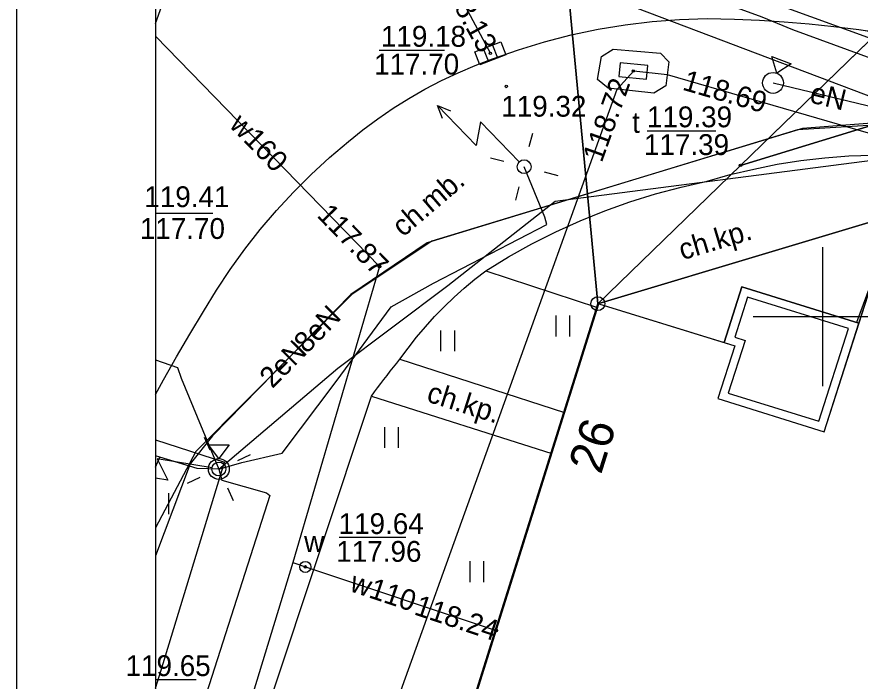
# Model space of a CAD drawing. Extents: x 6432121 to 6432331, y 5662538 to 5662686.
# Drawn here: x 6432120.98 to 6432151.36, y 5662586.88 to 5662610.8 of the extents above; entities that cross this region are included whole.
import ezdxf

# ---------------------------------------------------------------- set-up
doc = ezdxf.new("R2010")
doc.units = 0
for name, color, linetype in [('Warstwa 1', 7, 'Continuous'), ('Warstwa 10', 7, 'Continuous'), ('Warstwa 12', 7, 'Continuous'), ('Warstwa 13', 7, 'Continuous'), ('Warstwa 14', 7, 'Continuous'), ('Warstwa 15', 7, 'Continuous'), ('Warstwa 16', 7, 'Continuous'), ('Warstwa 2', 7, 'Continuous'), ('Warstwa 20', 7, 'Continuous'), ('Warstwa 25', 7, 'Continuous'), ('Warstwa 35', 7, 'Continuous'), ('Warstwa 4', 7, 'Continuous'), ('Warstwa 40', 7, 'Continuous'), ('Warstwa 5', 7, 'Continuous'), ('Warstwa 6', 7, 'Continuous'), ('Warstwa 63', 7, 'Continuous'), ('Warstwa 8', 7, 'Continuous'), ('Warstwa 9', 7, 'Continuous')]:
    doc.layers.add(name, color=color, linetype=linetype)

msp = doc.modelspace()

# ---------------------------------------------------------------- linework, layer by layer
at = {"layer": 'Warstwa 1'}
for p, q in [((6432136.954, 5662653.004), (6432141.907, 5662600.47)), ((6432136.954, 5662653.004), (6432141.907, 5662600.47)), ((6432147.05, 5662605.45), (6432164.332, 5662622.19)), ((6432147.05, 5662605.45), (6432164.332, 5662622.19)), ((6432147.05, 5662605.45), (6432180.9, 5662615.82)), ((6432147.05, 5662605.45), (6432180.9, 5662615.82)), ((6432141.907, 5662600.47), (6432147.05, 5662605.45)), ((6432141.907, 5662600.47), (6432147.05, 5662605.45)), ((6432141.907, 5662600.47), (6432155.186, 5662604.45)), ((6432141.907, 5662600.47), (6432155.186, 5662604.45)), ((6432128.788, 5662558.646), (6432141.907, 5662600.47)), ((6432128.788, 5662558.646), (6432141.907, 5662600.47))]:
    msp.add_line(p, q, dxfattribs=at)
msp.add_lwpolyline([(6432127.995, 5662556.053), (6432141.94, 5662600.47), (6432146.84, 5662598.95), (6432146.23, 5662597.05), (6432150.06, 5662595.86), (6432151.74, 5662601.09), (6432197.45, 5662586.76), (6432193.11, 5662572.86), (6432152.51, 5662585.63), (6432148.5, 5662572.83), (6432147.6, 5662573.08), (6432145.6, 5662566.71), (6432142.254, 5662556.053)], dxfattribs=at)
at = {"layer": 'Warstwa 10'}
msp.add_circle((6432141.907, 5662600.47), 0.25, dxfattribs=at)
at = {"layer": 'Warstwa 12'}
for points in [[(6432138.036, 5662609.488), (6432134.626, 5662615.865), (6432132.697, 5662619.588), (6432131.739, 5662621.489)], [(6432127.185, 5662618.897), (6432135.629, 5662615.848), (6432142.79, 5662613.281), (6432154.997, 5662608.849), (6432160.46, 5662606.879), (6432165.736, 5662604.745), (6432167.852, 5662603.89), (6432175.869, 5662600.716), (6432188.607, 5662595.673), (6432197.141, 5662592.258), (6432208.285, 5662587.853), (6432217.328, 5662584.25), (6432226.269, 5662580.703), (6432229.116, 5662579.575), (6432234.631, 5662577.404), (6432234.076, 5662575.247), (6432232.817, 5662570.334), (6432230.472, 5662561.671), (6432228.926, 5662556.053)], [(6432228.367, 5662556.053), (6432231.658, 5662568.249), (6432233.96, 5662576.659), (6432221.597, 5662581.652), (6432210.31, 5662586.256), (6432196.752, 5662591.605), (6432184.96, 5662596.314), (6432169.081, 5662602.651), (6432160.264, 5662606.196), (6432148.936, 5662610.33), (6432147.827, 5662610.792), (6432135.842, 5662615.166), (6432127.959, 5662618.065)], [(6432127.946, 5662615.962), (6432128.842, 5662616.521), (6432129.879, 5662616.161), (6432135.004, 5662614.244), (6432137.96, 5662613.1), (6432142.879, 5662611.278), (6432154.141, 5662607.021), (6432159.281, 5662605.095), (6432161.845, 5662604.079), (6432162.876, 5662603.668), (6432169.279, 5662601.311), (6432171.448, 5662600.465), (6432177.657, 5662598.132), (6432182.74, 5662596.197), (6432190.963, 5662593.097), (6432191.954, 5662592.706)], [(6432125.976, 5662610.557), (6432127.485, 5662614.793), (6432127.946, 5662615.962)], [(6432125.976, 5662610.102), (6432134.04, 5662601.81), (6432130.92, 5662591.15), (6432126.07, 5662575.26), (6432125.976, 5662574.953)], [(6432125.976, 5662559.881), (6432127.22, 5662563.81), (6432133.93, 5662584.09), (6432142.61, 5662608.19), (6432143.204, 5662608.85), (6432144.41, 5662608.72), (6432156.66, 5662605.17), (6432161.55, 5662603.82), (6432185, 5662594.71), (6432189.43, 5662592.42), (6432210.16, 5662585.32), (6432215.53, 5662583.54), (6432216.154, 5662583.288)], [(6432155.597, 5662608.32), (6432155.5, 5662607.86), (6432154.42, 5662607.05), (6432149.1, 5662606.73), (6432135.76, 5662602.66), (6432133.01, 5662600.8), (6432128.02, 5662595.71), (6432127.22, 5662594.7), (6432125.976, 5662591.383)], [(6432155.587, 5662608.308), (6432155.49, 5662607.98), (6432153.65, 5662607.11), (6432149.28, 5662606.78), (6432135.93, 5662602.72), (6432133.04, 5662600.8), (6432127.42, 5662595.15), (6432125.976, 5662592.393)], [(6432128.254, 5662594.515), (6432132.54, 5662598.15), (6432136.498, 5662601.127), (6432140.369, 5662604.156), (6432151.789, 5662605.642), (6432152.962, 5662605.787), (6432154.261, 5662607.985), (6432155.266, 5662607.612), (6432155.378, 5662607.878), (6432155.597, 5662608.32)], [(6432148.22, 5662608.42), (6432153.65, 5662607.11), (6432155.49, 5662607.98), (6432155.587, 5662608.308)], [(6432128.254, 5662594.515), (6432129.083, 5662594.753), (6432130.54, 5662595.089), (6432132.478, 5662597.669), (6432134.467, 5662600.362), (6432135.993, 5662601.204), (6432140.071, 5662603.327), (6432139.999, 5662603.585), (6432139.251, 5662605.402)], [(6432152.099, 5662602.16), (6432151.23, 5662599.79)], [(6432125.976, 5662598.445), (6432126.766, 5662598.169), (6432126.89, 5662597.793), (6432128.254, 5662594.515)], [(6432126.133, 5662594.937), (6432125.976, 5662594.984)], [(6432125.976, 5662594.576), (6432126.133, 5662594.937)], [(6432128.254, 5662594.515), (6432127.475, 5662594.536), (6432126.133, 5662594.937)], [(6432128.254, 5662594.515), (6432128.361, 5662594.113), (6432129.97, 5662593.659), (6432130.096, 5662593.561), (6432127.399, 5662585.174), (6432125.976, 5662580.765)], [(6432130.92, 5662591.15), (6432131.37, 5662590.99), (6432138.244, 5662588.699)]]:
    msp.add_lwpolyline(points, dxfattribs=at)
msp.add_circle((6432147.05, 5662605.45), 0.045, dxfattribs=at)
at = {"layer": 'Warstwa 14'}
for p, q in [((6432134.032, 5662609.598), (6432136.387, 5662609.598)), ((6432143.682, 5662606.698), (6432146.155, 5662606.698)), ((6432125.976, 5662603.734), (6432128.034, 5662603.734)), ((6432134.995, 5662592.05), (6432132.594, 5662592.05)), ((6432125.976, 5662586.933), (6432127.442, 5662586.933))]:
    msp.add_line(p, q, dxfattribs=at)
for centre in [(6432138.036, 5662609.488), (6432138.036, 5662609.488), (6432138.036, 5662609.488), (6432143.185, 5662608.847), (6432143.185, 5662608.847), (6432143.185, 5662608.847), (6432143.185, 5662608.847), (6432134.04, 5662601.81), (6432131.37, 5662590.99), (6432131.37, 5662590.99), (6432138.244, 5662588.699)]:
    msp.add_circle(centre, 0.045, dxfattribs=at)
at = {"layer": 'Warstwa 16'}
msp.add_lwpolyline([(6432142.46, 5662609.63), (6432144.17, 5662609.49), (6432144.47, 5662609.18), (6432144.36, 5662608.31), (6432143.93, 5662608.05), (6432142.28, 5662608.23), (6432141.9, 5662608.54), (6432142.04, 5662609.37)], close=True, dxfattribs=at)
at = {"layer": 'Warstwa 2'}
for centre in [(6432139.251, 5662605.402), (6432128.254, 5662594.515)]:
    msp.add_circle(centre, 0.25, dxfattribs=at)
at = {"layer": 'Warstwa 20'}
msp.add_line((6432138.323, 5662588.936), (6432138.165, 5662588.462), dxfattribs=at)
at = {"layer": 'Warstwa 25'}
msp.add_circle((6432138.611, 5662608.293), 0.045, dxfattribs=at)
at = {"layer": 'Warstwa 35'}
for points in [[(6432151.315, 5662599.768), (6432147.1, 5662601.08), (6432146.462, 5662599.067), (6432146.84, 5662598.95), (6432146.23, 5662597.05), (6432150.06, 5662595.86)], [(6432150.937, 5662599.571), (6432147.296, 5662600.705), (6432146.839, 5662599.264), (6432147.218, 5662599.147), (6432146.608, 5662597.247), (6432149.865, 5662596.235)]]:
    msp.add_lwpolyline(points, close=True, dxfattribs=at)
at = {"layer": 'Warstwa 4'}
for p, q in [((6432137.782, 5662609.657), (6432137.964, 5662609.191)), ((6432138.108, 5662609.785), (6432138.29, 5662609.319))]:
    msp.add_line(p, q, dxfattribs=at)
for points in [[(6432137.479, 5662609.539), (6432138.411, 5662609.903), (6432138.593, 5662609.437), (6432137.661, 5662609.073)], [(6432143.707, 5662609.047), (6432142.712, 5662609.144), (6432142.663, 5662608.647), (6432143.658, 5662608.55)]]:
    msp.add_lwpolyline(points, close=True, dxfattribs=at)
for points in [[(6432139.439, 5662606.128), (6432139.564, 5662606.612)], [(6432138.525, 5662605.59), (6432138.041, 5662605.715)], [(6432139.977, 5662605.214), (6432140.461, 5662605.089)], [(6432139.063, 5662604.676), (6432138.938, 5662604.192)], [(6432127.995, 5662556.053), (6432141.94, 5662600.47), (6432146.84, 5662598.95), (6432146.23, 5662597.05), (6432150.06, 5662595.86), (6432151.74, 5662601.09), (6432197.45, 5662586.76), (6432193.11, 5662572.86), (6432152.51, 5662585.63), (6432148.5, 5662572.83), (6432147.6, 5662573.08), (6432142.254, 5662556.053)], [(6432127.943, 5662595.197), (6432127.735, 5662595.652)], [(6432128.936, 5662594.826), (6432129.391, 5662595.034)], [(6432127.572, 5662594.204), (6432127.117, 5662593.996)], [(6432128.565, 5662593.833), (6432128.773, 5662593.378)]]:
    msp.add_lwpolyline(points, dxfattribs=at)
msp.add_circle((6432131.37, 5662590.99), 0.2, dxfattribs=at)
at = {"layer": 'Warstwa 40'}
for points in [[(6432148.352, 5662608.771), (6432148.176, 5662609.371), (6432148.878, 5662609.108)], [(6432128.254, 5662594.89), (6432127.879, 5662595.39), (6432128.629, 5662595.39)]]:
    msp.add_lwpolyline(points, close=True, dxfattribs=at)
for points in [[(6432139.077, 5662605.581), (6432137.683, 5662607.016), (6432137.529, 5662606.169), (6432136.136, 5662607.604)], [(6432136.316, 5662607.137), (6432136.136, 5662607.604), (6432136.597, 5662607.41)], [(6432128.007, 5662594.556), (6432126.034, 5662594.884), (6432126.413, 5662594.111), (6432125.976, 5662594.184)]]:
    msp.add_lwpolyline(points, dxfattribs=at)
for centre, radius in [((6432148.22, 5662608.42), 0.375), ((6432139.251, 5662605.402), 0.25), ((6432128.254, 5662594.515), 0.375), ((6432128.254, 5662594.515), 0.25)]:
    msp.add_circle(centre, radius, dxfattribs=at)
at = {"layer": 'Warstwa 5'}
for p, q in [((6432137.478, 5662601.348), (6432137.87, 5662601.65)), ((6432137.87, 5662601.65), (6432141.897, 5662600.334)), ((6432137.097, 5662601.032), (6432137.478, 5662601.348)), ((6432136.728, 5662600.703), (6432137.097, 5662601.032)), ((6432136.371, 5662600.361), (6432136.728, 5662600.703)), ((6432136.026, 5662600.006), (6432136.371, 5662600.361)), ((6432140.71, 5662596.553), (6432141.897, 5662600.334)), ((6432135.694, 5662599.639), (6432136.026, 5662600.006)), ((6432140.402, 5662599.292), (6432140.402, 5662600.042)), ((6432140.902, 5662599.292), (6432140.902, 5662600.042)), ((6432135.375, 5662599.26), (6432135.694, 5662599.639)), ((6432136.254, 5662598.755), (6432136.254, 5662599.505)), ((6432136.754, 5662598.755), (6432136.754, 5662599.505)), ((6432135.071, 5662598.871), (6432135.375, 5662599.26)), ((6432134.78, 5662598.47), (6432135.071, 5662598.871)), ((6432134.78, 5662598.47), (6432140.71, 5662596.553)), ((6432125.976, 5662573.776), (6432133.75, 5662597.14)), ((6432133.75, 5662597.14), (6432140.245, 5662595.072)), ((6432134.232, 5662595.277), (6432134.232, 5662596.027)), ((6432134.732, 5662595.277), (6432134.732, 5662596.027)), ((6432125.976, 5662595.561), (6432128.463, 5662594.756)), ((6432127.995, 5662556.053), (6432140.245, 5662595.072)), ((6432126.164, 5662587.231), (6432128.463, 5662594.756)), ((6432126.449, 5662592.89), (6432126.449, 5662593.64)), ((6432137.304, 5662590.444), (6432137.304, 5662591.194)), ((6432137.804, 5662590.444), (6432137.804, 5662591.194)), ((6432125.976, 5662586.625), (6432126.164, 5662587.231))]:
    msp.add_line(p, q, dxfattribs=at)
at = {"layer": 'Warstwa 6'}
for points in [[(6432234.842, 5662644.244), (6432245.39, 5662639.916), (6432244.087, 5662648.722), (6432241.262, 5662679.658), (6432232.544, 5662677.413), (6432183.398, 5662664.76), (6432164.325, 5662660.371), (6432136.954, 5662653.004), (6432141.907, 5662600.47), (6432147.05, 5662605.45), (6432164.332, 5662622.19), (6432166.394, 5662623.975)], [(6432164.332, 5662622.19), (6432147.05, 5662605.45), (6432180.9, 5662615.82)], [(6432180.9, 5662615.82), (6432147.05, 5662605.45), (6432141.907, 5662600.47), (6432155.186, 5662604.45), (6432246.621, 5662569.177), (6432269.007, 5662560.534), (6432263.163, 5662588.197), (6432259.074, 5662585.787)]]:
    msp.add_lwpolyline(points, close=True, dxfattribs=at)
for points in [[(6432127.651, 5662556.053), (6432128.788, 5662558.646), (6432141.907, 5662600.47), (6432136.954, 5662653.004), (6432125.976, 5662650.322)], [(6432138.114, 5662609.287), (6432139.045, 5662609.616), (6432139.991, 5662609.903), (6432140.948, 5662610.148), (6432141.915, 5662610.352), (6432142.89, 5662610.512), (6432143.871, 5662610.629), (6432144.856, 5662610.704), (6432145.844, 5662610.735), (6432146.832, 5662610.722)], [(6432146.832, 5662610.722), (6432147.73, 5662610.683), (6432148.626, 5662610.625), (6432149.521, 5662610.549), (6432150.415, 5662610.453), (6432151.306, 5662610.339), (6432152.194, 5662610.206), (6432153.08, 5662610.054), (6432153.962, 5662609.883), (6432154.84, 5662609.694)], [(6432132.928, 5662606.31), (6432133.447, 5662606.729), (6432133.983, 5662607.128), (6432134.534, 5662607.505), (6432135.1, 5662607.861), (6432135.679, 5662608.193), (6432136.271, 5662608.502), (6432136.875, 5662608.788), (6432137.489, 5662609.05), (6432138.114, 5662609.287)], [(6432127.703, 5662600.183), (6432128.169, 5662600.953), (6432128.666, 5662601.703), (6432129.192, 5662602.432), (6432129.748, 5662603.14), (6432130.331, 5662603.824), (6432130.942, 5662604.485), (6432131.579, 5662605.12), (6432132.242, 5662605.729), (6432132.928, 5662606.31)], [(6432249.006, 5662556.053), (6432246.621, 5662569.177), (6432155.186, 5662604.45), (6432141.907, 5662600.47), (6432128.788, 5662558.646), (6432132.46, 5662567.032), (6432163.983, 5662578.631), (6432172.647, 5662574.865), (6432180.454, 5662556.053)], [(6432125.976, 5662597.203), (6432126.258, 5662597.729), (6432126.723, 5662598.557), (6432127.205, 5662599.375), (6432127.703, 5662600.183)]]:
    msp.add_lwpolyline(points, dxfattribs=at)
at = {"layer": 'Warstwa 63'}
for p, q in [((6432150, 5662602.5), (6432150, 5662597.5)), ((6432152.5, 5662600), (6432147.5, 5662600))]:
    msp.add_line(p, q, dxfattribs=at)
for points in [[(6432120.976, 5662686.053), (6432330.976, 5662686.053), (6432330.976, 5662537.553), (6432120.976, 5662537.553)], [(6432125.976, 5662556.053), (6432325.976, 5662556.053), (6432325.976, 5662681.053), (6432125.976, 5662681.053)]]:
    msp.add_lwpolyline(points, close=True, dxfattribs=at)
at = {"layer": 'Warstwa 8'}
for p, q in [((6432144.856, 5662610.704), (6432145.844, 5662610.735)), ((6432145.844, 5662610.735), (6432146.832, 5662610.722)), ((6432141.915, 5662610.352), (6432142.89, 5662610.512)), ((6432142.89, 5662610.512), (6432143.871, 5662610.629)), ((6432143.871, 5662610.629), (6432144.856, 5662610.704)), ((6432146.832, 5662610.722), (6432147.73, 5662610.683)), ((6432147.73, 5662610.683), (6432148.626, 5662610.625)), ((6432148.626, 5662610.625), (6432149.521, 5662610.549)), ((6432149.521, 5662610.549), (6432150.415, 5662610.453)), ((6432150.415, 5662610.453), (6432151.306, 5662610.339)), ((6432139.991, 5662609.903), (6432140.948, 5662610.148)), ((6432140.948, 5662610.148), (6432141.915, 5662610.352)), ((6432151.306, 5662610.339), (6432152.194, 5662610.206)), ((6432139.045, 5662609.616), (6432139.991, 5662609.903)), ((6432138.114, 5662609.287), (6432139.045, 5662609.616)), ((6432137.489, 5662609.05), (6432138.114, 5662609.287)), ((6432136.875, 5662608.788), (6432137.489, 5662609.05)), ((6432136.271, 5662608.502), (6432136.875, 5662608.788)), ((6432135.679, 5662608.193), (6432136.271, 5662608.502)), ((6432135.1, 5662607.861), (6432135.679, 5662608.193)), ((6432134.534, 5662607.505), (6432135.1, 5662607.861)), ((6432133.983, 5662607.128), (6432134.534, 5662607.505)), ((6432133.447, 5662606.729), (6432133.983, 5662607.128)), ((6432132.928, 5662606.31), (6432133.447, 5662606.729)), ((6432132.242, 5662605.729), (6432132.928, 5662606.31)), ((6432131.579, 5662605.12), (6432132.242, 5662605.729)), ((6432130.942, 5662604.485), (6432131.579, 5662605.12)), ((6432130.331, 5662603.824), (6432130.942, 5662604.485)), ((6432129.748, 5662603.14), (6432130.331, 5662603.824)), ((6432129.192, 5662602.432), (6432129.748, 5662603.14)), ((6432128.666, 5662601.703), (6432129.192, 5662602.432)), ((6432128.169, 5662600.953), (6432128.666, 5662601.703)), ((6432127.703, 5662600.183), (6432128.169, 5662600.953)), ((6432127.205, 5662599.375), (6432127.703, 5662600.183)), ((6432126.723, 5662598.557), (6432127.205, 5662599.375)), ((6432126.258, 5662597.729), (6432126.723, 5662598.557)), ((6432125.976, 5662597.203), (6432126.258, 5662597.729))]:
    msp.add_line(p, q, dxfattribs=at)
at = {"layer": 'Warstwa 9'}
for p, q in [((6432144.856, 5662610.704), (6432145.844, 5662610.735)), ((6432145.844, 5662610.735), (6432146.832, 5662610.722)), ((6432141.915, 5662610.352), (6432142.89, 5662610.512)), ((6432142.89, 5662610.512), (6432143.871, 5662610.629)), ((6432143.871, 5662610.629), (6432144.856, 5662610.704)), ((6432146.832, 5662610.722), (6432147.73, 5662610.683)), ((6432147.73, 5662610.683), (6432148.626, 5662610.625)), ((6432148.626, 5662610.625), (6432149.521, 5662610.549)), ((6432149.521, 5662610.549), (6432150.415, 5662610.453)), ((6432150.415, 5662610.453), (6432151.306, 5662610.339)), ((6432139.991, 5662609.903), (6432140.948, 5662610.148)), ((6432140.948, 5662610.148), (6432141.915, 5662610.352)), ((6432151.306, 5662610.339), (6432152.194, 5662610.206)), ((6432139.045, 5662609.616), (6432139.991, 5662609.903)), ((6432138.114, 5662609.287), (6432139.045, 5662609.616)), ((6432137.489, 5662609.05), (6432138.114, 5662609.287)), ((6432136.875, 5662608.788), (6432137.489, 5662609.05)), ((6432136.271, 5662608.502), (6432136.875, 5662608.788)), ((6432135.679, 5662608.193), (6432136.271, 5662608.502)), ((6432135.1, 5662607.861), (6432135.679, 5662608.193)), ((6432134.534, 5662607.505), (6432135.1, 5662607.861)), ((6432133.983, 5662607.128), (6432134.534, 5662607.505)), ((6432133.447, 5662606.729), (6432133.983, 5662607.128)), ((6432132.928, 5662606.31), (6432133.447, 5662606.729)), ((6432132.242, 5662605.729), (6432132.928, 5662606.31)), ((6432131.579, 5662605.12), (6432132.242, 5662605.729)), ((6432148.371, 5662605.489), (6432149.225, 5662605.624)), ((6432148.371, 5662605.489), (6432149.225, 5662605.624)), ((6432149.225, 5662605.624), (6432150.084, 5662605.725)), ((6432149.225, 5662605.624), (6432150.084, 5662605.725)), ((6432150.084, 5662605.725), (6432150.947, 5662605.791)), ((6432150.084, 5662605.725), (6432150.947, 5662605.791)), ((6432150.947, 5662605.791), (6432151.811, 5662605.822)), ((6432150.947, 5662605.791), (6432151.811, 5662605.822)), ((6432146.682, 5662605.117), (6432147.523, 5662605.32)), ((6432146.682, 5662605.117), (6432147.523, 5662605.32)), ((6432147.523, 5662605.32), (6432148.371, 5662605.489)), ((6432147.523, 5662605.32), (6432148.371, 5662605.489)), ((6432130.942, 5662604.485), (6432131.579, 5662605.12)), ((6432145.85, 5662604.88), (6432146.682, 5662605.117)), ((6432145.85, 5662604.88), (6432146.682, 5662605.117)), ((6432143.982, 5662604.421), (6432144.911, 5662604.67)), ((6432143.982, 5662604.421), (6432144.911, 5662604.67)), ((6432144.911, 5662604.67), (6432145.85, 5662604.88)), ((6432144.911, 5662604.67), (6432145.85, 5662604.88)), ((6432130.331, 5662603.824), (6432130.942, 5662604.485)), ((6432143.064, 5662604.135), (6432143.982, 5662604.421)), ((6432143.064, 5662604.135), (6432143.982, 5662604.421)), ((6432142.158, 5662603.811), (6432143.064, 5662604.135)), ((6432142.158, 5662603.811), (6432143.064, 5662604.135)), ((6432129.748, 5662603.14), (6432130.331, 5662603.824)), ((6432141.266, 5662603.45), (6432142.158, 5662603.811)), ((6432141.266, 5662603.45), (6432142.158, 5662603.811)), ((6432140.39, 5662603.053), (6432141.266, 5662603.45)), ((6432140.39, 5662603.053), (6432141.266, 5662603.45)), ((6432129.192, 5662602.432), (6432129.748, 5662603.14)), ((6432139.531, 5662602.62), (6432140.39, 5662603.053)), ((6432139.531, 5662602.62), (6432140.39, 5662603.053)), ((6432138.691, 5662602.152), (6432139.531, 5662602.62)), ((6432138.691, 5662602.152), (6432139.531, 5662602.62)), ((6432128.666, 5662601.703), (6432129.192, 5662602.432)), ((6432137.87, 5662601.65), (6432138.691, 5662602.152)), ((6432137.87, 5662601.65), (6432138.691, 5662602.152)), ((6432128.169, 5662600.953), (6432128.666, 5662601.703)), ((6432137.478, 5662601.348), (6432137.87, 5662601.65)), ((6432137.87, 5662601.65), (6432141.897, 5662600.334)), ((6432137.097, 5662601.032), (6432137.478, 5662601.348)), ((6432136.728, 5662600.703), (6432137.097, 5662601.032)), ((6432146.462, 5662599.067), (6432147.1, 5662601.08)), ((6432147.1, 5662601.08), (6432151.315, 5662599.768)), ((6432151.315, 5662599.768), (6432151.74, 5662601.09)), ((6432127.703, 5662600.183), (6432128.169, 5662600.953)), ((6432136.371, 5662600.361), (6432136.728, 5662600.703)), ((6432141.897, 5662600.334), (6432141.94, 5662600.47)), ((6432141.94, 5662600.47), (6432146.462, 5662599.067)), ((6432127.205, 5662599.375), (6432127.703, 5662600.183)), ((6432136.026, 5662600.006), (6432136.371, 5662600.361)), ((6432135.694, 5662599.639), (6432136.026, 5662600.006)), ((6432135.375, 5662599.26), (6432135.694, 5662599.639)), ((6432126.723, 5662598.557), (6432127.205, 5662599.375)), ((6432135.071, 5662598.871), (6432135.375, 5662599.26)), ((6432134.78, 5662598.47), (6432135.071, 5662598.871)), ((6432126.258, 5662597.729), (6432126.723, 5662598.557)), ((6432134.544, 5662598.18), (6432134.662, 5662598.326)), ((6432134.544, 5662598.18), (6432134.662, 5662598.326)), ((6432134.662, 5662598.326), (6432134.78, 5662598.47)), ((6432134.662, 5662598.326), (6432134.78, 5662598.47)), ((6432134.78, 5662598.47), (6432140.71, 5662596.553)), ((6432134.312, 5662597.887), (6432134.428, 5662598.034)), ((6432134.312, 5662597.887), (6432134.428, 5662598.034)), ((6432134.428, 5662598.034), (6432134.544, 5662598.18)), ((6432134.428, 5662598.034), (6432134.544, 5662598.18)), ((6432125.976, 5662597.203), (6432126.258, 5662597.729)), ((6432134.084, 5662597.591), (6432134.198, 5662597.739)), ((6432134.084, 5662597.591), (6432134.198, 5662597.739)), ((6432134.198, 5662597.739), (6432134.312, 5662597.887)), ((6432134.198, 5662597.739), (6432134.312, 5662597.887)), ((6432133.86, 5662597.291), (6432133.972, 5662597.441)), ((6432133.86, 5662597.291), (6432133.972, 5662597.441)), ((6432133.972, 5662597.441), (6432134.084, 5662597.591)), ((6432133.972, 5662597.441), (6432134.084, 5662597.591)), ((6432125.976, 5662573.776), (6432133.75, 5662597.14)), ((6432133.75, 5662597.14), (6432133.86, 5662597.291)), ((6432133.75, 5662597.14), (6432133.86, 5662597.291)), ((6432133.75, 5662597.14), (6432140.245, 5662595.072)), ((6432140.245, 5662595.072), (6432140.71, 5662596.553)), ((6432125.976, 5662595.561), (6432128.463, 5662594.756)), ((6432126.164, 5662587.231), (6432128.463, 5662594.756)), ((6432125.976, 5662586.625), (6432126.164, 5662587.231))]:
    msp.add_line(p, q, dxfattribs=at)

# ---------------------------------------------------------------- texts
at = {"layer": 'Warstwa 13'}
for s, rotation, p in [('eN', 346.4389, (6432149.501, 5662607.725)), ('w160', 314.1986, (6432128.597, 5662606.87)), ('8eN', 45.5673, (6432131.42, 5662598.642)), ('2eN', 45.1548, (6432130.177, 5662597.39)), ('w110', 341.5631, (6432132.929, 5662590.129))]:
    msp.add_text(s, height=0.75, rotation=rotation, dxfattribs=at).set_placement(p)
at = {"layer": 'Warstwa 14'}
for s, height, rotation, p in [('118.13', 0.75, 298.8376, (6432136.18, 5662612.134)), ('118.69', 0.75, 343.8377, (6432144.92, 5662608.182)), ('118.72', 0.75, 70.1931, (6432142.049, 5662605.525)), ('117.87', 0.75, 314.1986, (6432131.753, 5662603.625)), ('26', 1.25, 72.5823, (6432142.022, 5662594.291)), ('118.24', 0.75, 341.5631, (6432135.254, 5662589.287))]:
    msp.add_text(s, height=height, rotation=rotation, dxfattribs=at).set_placement(p)
for s, p in [('117.70', (6432133.846, 5662608.723)), ('117.39', (6432143.569, 5662605.823)), ('117.70', (6432125.407, 5662602.802)), ('117.96', (6432132.486, 5662591.174))]:
    msp.add_text(s, height=0.75, dxfattribs=at).set_placement(p)
at = {"layer": 'Warstwa 15'}
for s, p in [('119.18', (6432134.092, 5662609.723)), ('119.39', (6432143.677, 5662606.823)), ('119.41', (6432125.568, 5662603.947)), ('119.64', (6432132.568, 5662592.174)), ('119.65', (6432124.892, 5662587.058))]:
    msp.add_text(s, height=0.75, dxfattribs=at).set_placement(p)
at = {"layer": 'Warstwa 25'}
msp.add_text('119.32', height=0.75, dxfattribs=at).set_placement((6432138.428, 5662607.205))
at = {"layer": 'Warstwa 5'}
for s, p in [('t', (6432143.144, 5662606.624)), ('w', (6432131.325, 5662591.523))]:
    msp.add_text(s, height=0.75, dxfattribs=at).set_placement(p)
at = {"layer": 'Warstwa 9'}
for s, rotation, p in [('ch.mb.', 40.5482, (6432134.892, 5662602.846)), ('ch.kp.', 16.6845, (6432144.956, 5662602.033)), ('ch.kp.', 342.3366, (6432135.699, 5662596.96))]:
    msp.add_text(s, height=0.75, rotation=rotation, dxfattribs=at).set_placement(p)

doc.saveas('drawing.dxf')
